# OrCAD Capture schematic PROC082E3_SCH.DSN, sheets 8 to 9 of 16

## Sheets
8 12. FPD LINK_CAM_IN5-8: size C; title: FPD Link Camera  Inputs 5-8
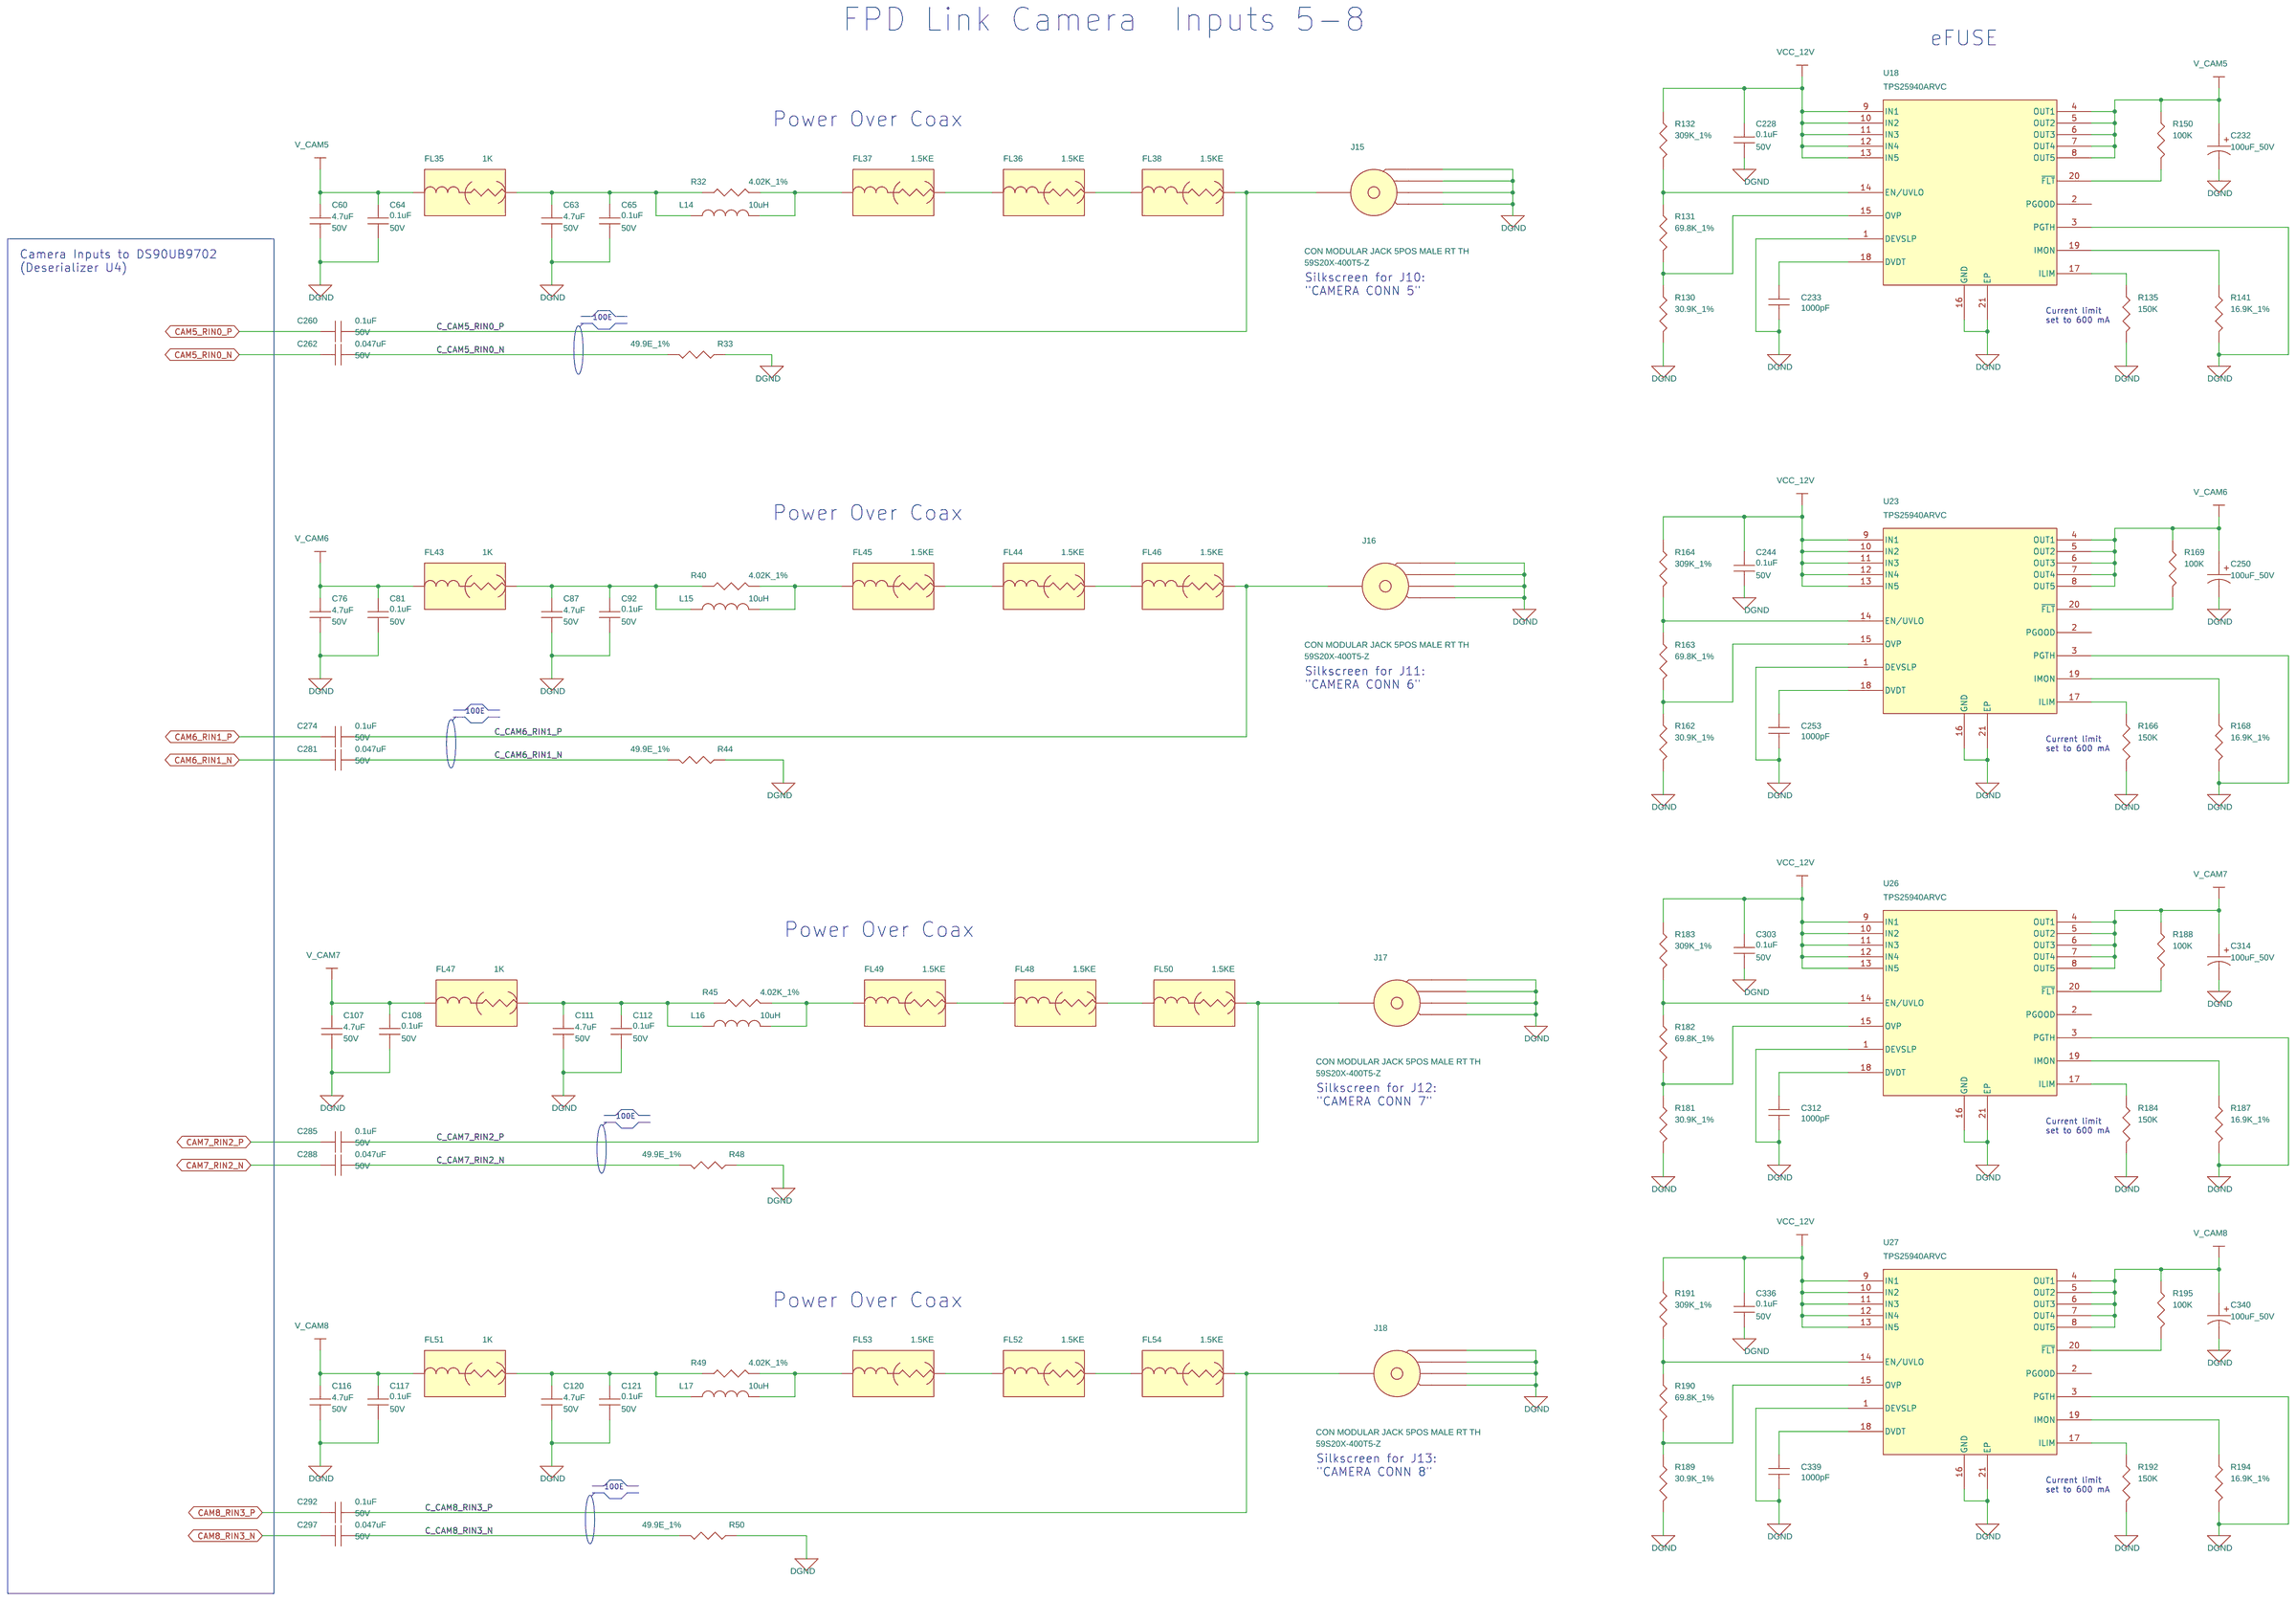
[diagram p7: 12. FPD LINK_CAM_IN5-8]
9 13. FPD LINK_CAM_IN9-12: size C; title: FPD Link Camera  Inputs 5-8
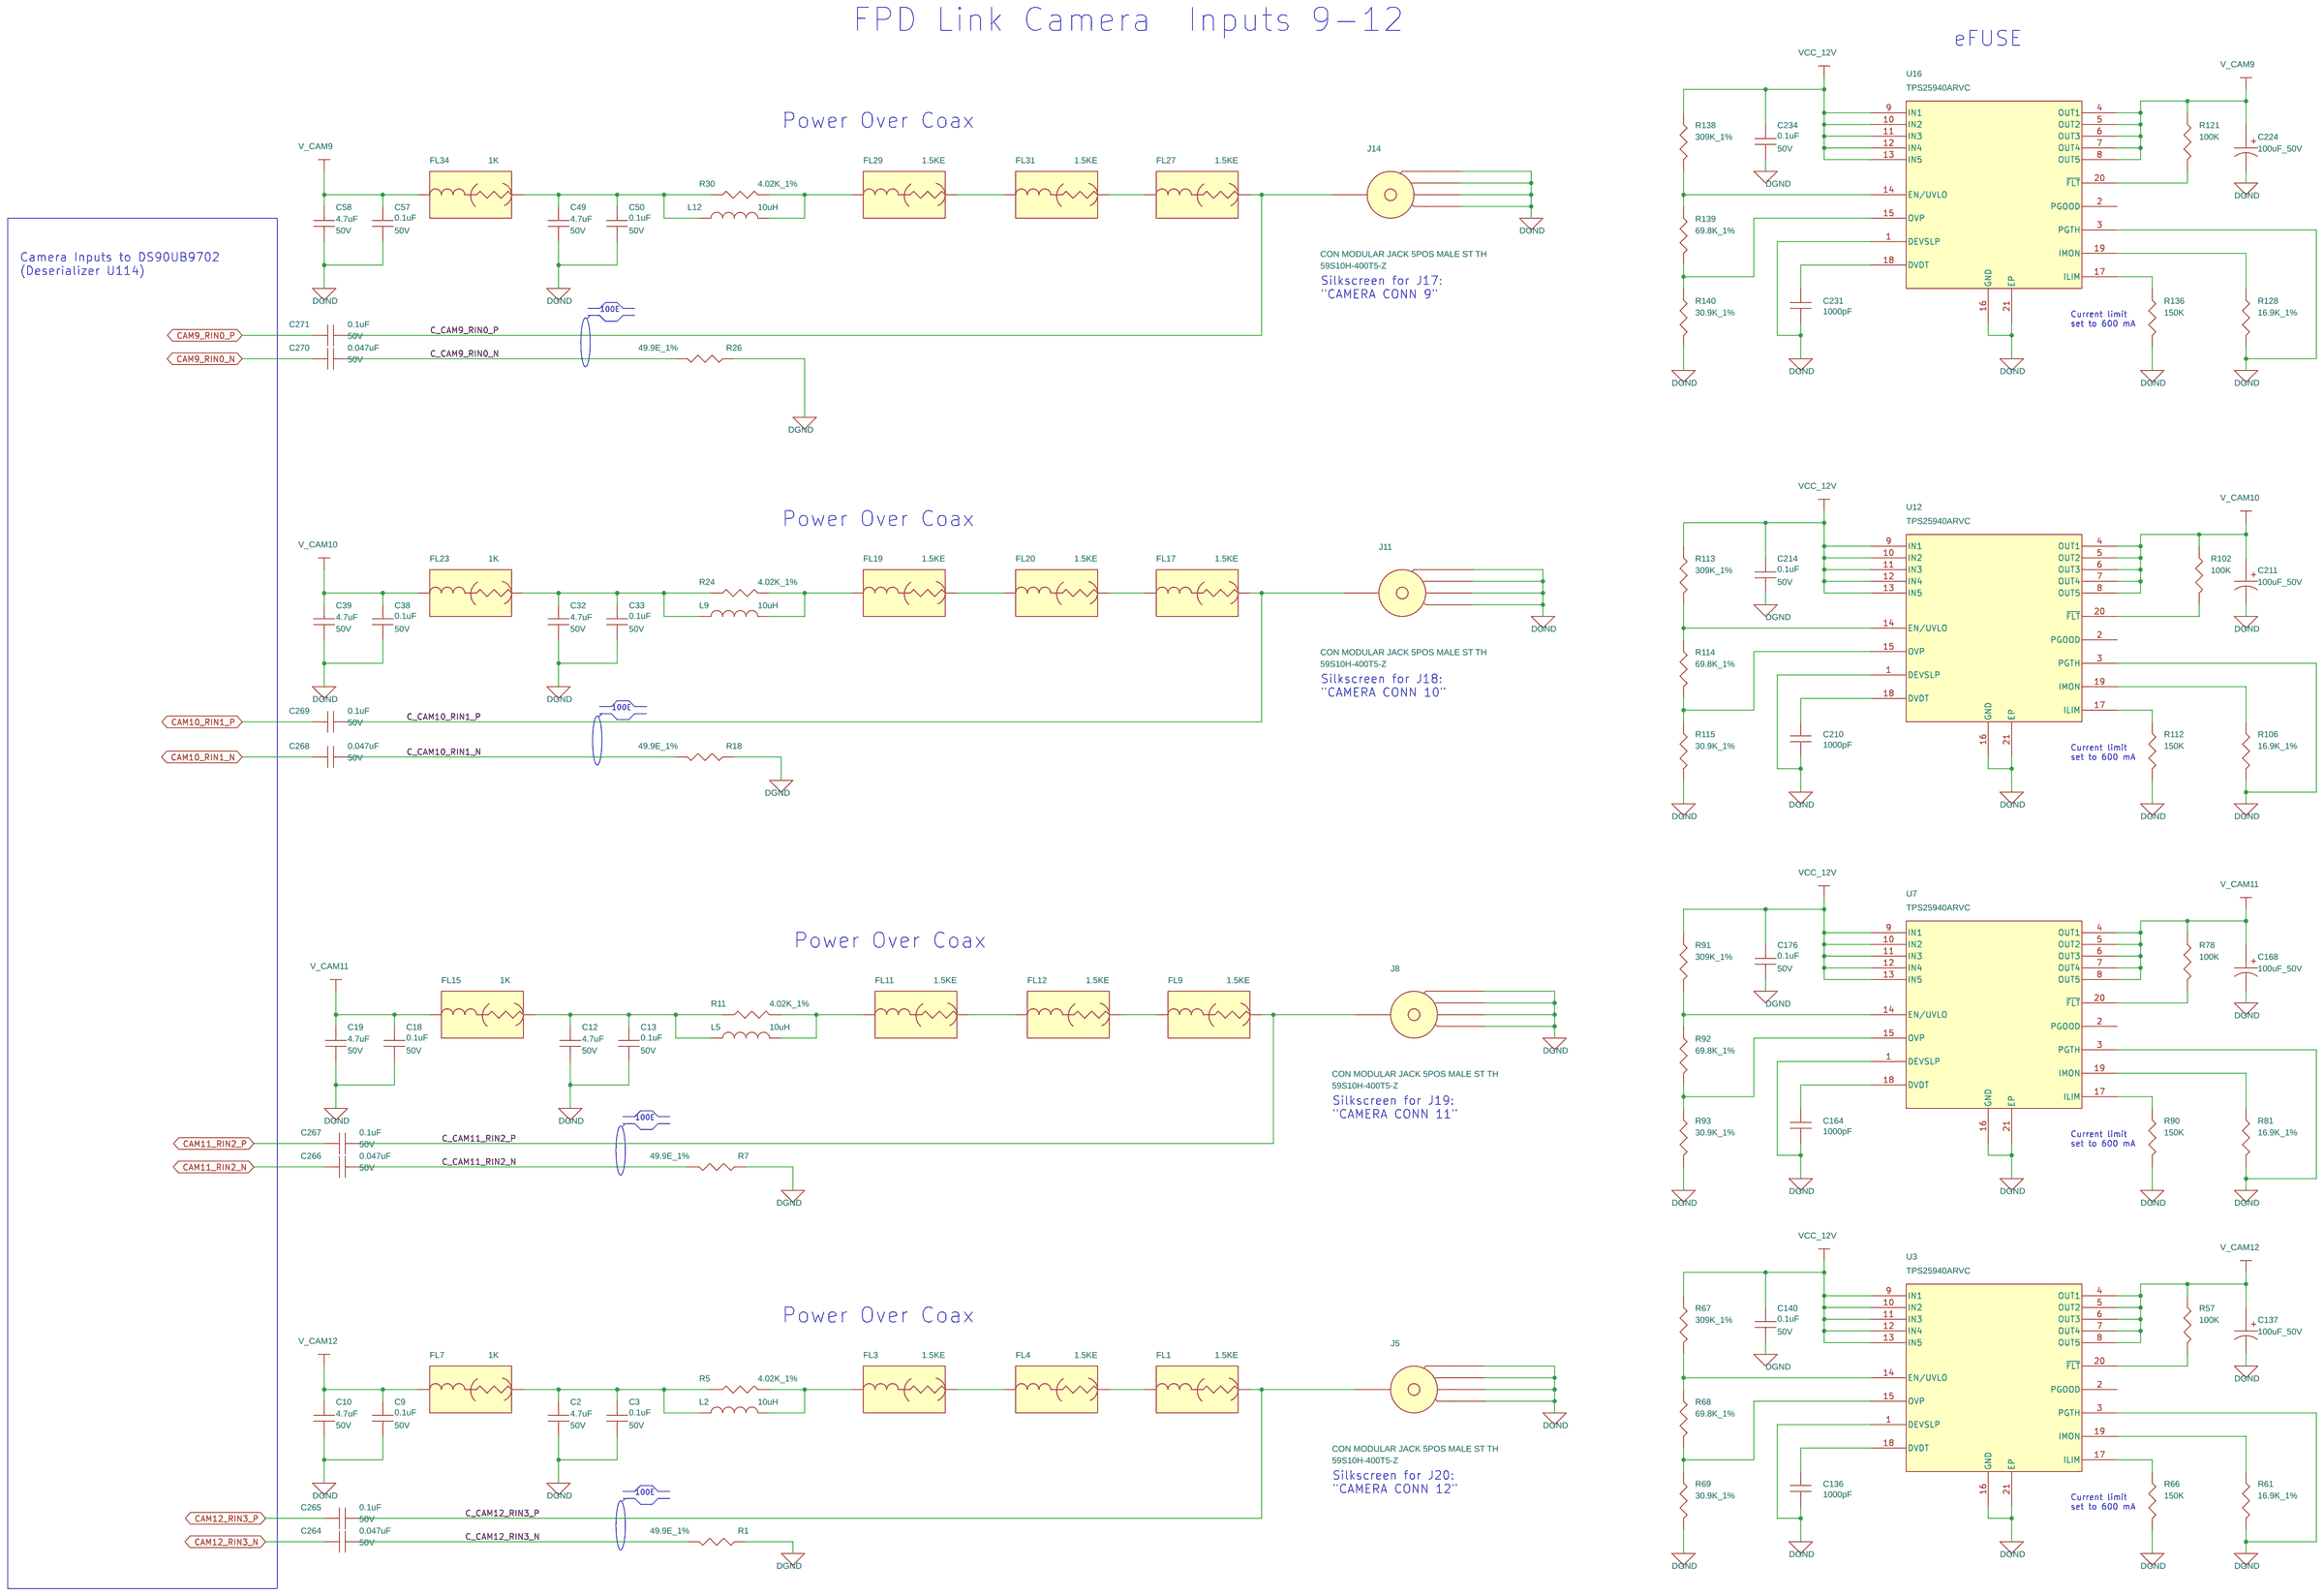
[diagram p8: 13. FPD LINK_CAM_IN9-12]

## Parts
sheet 12. FPD LINK_CAM_IN5-8
C60  4.7uF  [CAP1206_2]
C63  4.7uF  [CAP1206_2]
C64  0.1uF  [CAP0402_0-75]
C65  0.1uF  [CAP0402_0-75]
C76  4.7uF  [CAP1206_2]
C81  0.1uF  [CAP0402_0-75]
C87  4.7uF  [CAP1206_2]
C92  0.1uF  [CAP0402_0-75]
C107  4.7uF  [CAP1206_2]
C108  0.1uF  [CAP0402_0-75]
C111  4.7uF  [CAP1206_2]
C112  0.1uF  [CAP0402_0-75]
C116  4.7uF  [CAP1206_2]
C117  0.1uF  [CAP0402_0-75]
C120  4.7uF  [CAP1206_2]
C121  0.1uF  [CAP0402_0-75]
C228  0.1uF  [CAP0402_0-75]
C232  100uF_50V  [CAPAE_D8CASE_8]
C233  1000pF  [CAP0402_0-75]
C244  0.1uF  [CAP0402_0-75]
C250  100uF_50V  [CAPAE_D8CASE_8]
C253  1000pF  [CAP0402_0-75]
C260  0.1uF  [CAP0402_0-75]
C262  0.047uF  [CAP0402_0-75]
C274  0.1uF  [CAP0402_0-75]
C281  0.047uF  [CAP0402_0-75]
C285  0.1uF  [CAP0402_0-75]
C288  0.047uF  [CAP0402_0-75]
C292  0.1uF  [CAP0402_0-75]
C297  0.047uF  [CAP0402_0-75]
C303  0.1uF  [CAP0402_0-75]
C312  1000pF  [CAP0402_0-75]
C314  100uF_50V  [CAPAE_D8CASE_8]
C336  0.1uF  [CAP0402_0-75]
C339  1000pF  [CAP0402_0-75]
C340  100uF_50V  [CAPAE_D8CASE_8]
FL35  1K  [EMIFIL_BLM18A_0603_1]
FL36  1.5KE  [EMIFIL_BLM18R_0603]
FL37  1.5KE  [EMIFIL_BLM18R_0603]
FL38  1.5KE  [EMIFIL_BLM18R_0603]
FL43  1K  [EMIFIL_BLM18A_0603_1]
FL44  1.5KE  [EMIFIL_BLM18R_0603]
FL45  1.5KE  [EMIFIL_BLM18R_0603]
FL46  1.5KE  [EMIFIL_BLM18R_0603]
FL47  1K  [EMIFIL_BLM18A_0603_1]
FL48  1.5KE  [EMIFIL_BLM18R_0603]
FL49  1.5KE  [EMIFIL_BLM18R_0603]
FL50  1.5KE  [EMIFIL_BLM18R_0603]
FL51  1K  [EMIFIL_BLM18A_0603_1]
FL52  1.5KE  [EMIFIL_BLM18R_0603]
FL53  1.5KE  [EMIFIL_BLM18R_0603]
FL54  1.5KE  [EMIFIL_BLM18R_0603]
J15  CON_JACK5_59S20X-400T5  [CON_JACK5_59S20X-400T5-Z_P_R_T_10-1]
J16  CON_JACK5_59S20X-400T5  [CON_JACK5_59S20X-400T5-Z_P_R_T_10-1]
J17  CON_JACK5_59S20X-400T5  [CON_JACK5_59S20X-400T5-Z_P_R_T_10-1]
J18  CON_JACK5_59S20X-400T5  [CON_JACK5_59S20X-400T5-Z_P_R_T_10-1]
L14  10uH  [IND_MLZ2012N_90X60_SMD]
L15  10uH  [IND_MLZ2012N_90X60_SMD]
L16  10uH  [IND_MLZ2012N_90X60_SMD]
L17  10uH  [IND_MLZ2012N_90X60_SMD]
R32  4.02K_1%  [RES0603_0-5]
R33  49.9E_1%  [RES0402_0-5]
R40  4.02K_1%  [RES0603_0-5]
R44  49.9E_1%  [RES0402_0-5]
R45  4.02K_1%  [RES0603_0-5]
R48  49.9E_1%  [RES0402_0-5]
R49  4.02K_1%  [RES0603_0-5]
R50  49.9E_1%  [RES0402_0-5]
R130  30.9K_1%  [RES0402_0-5]
R131  69.8K_1%  [RES0402_0-5]
R132  309K_1%  [RES0402_0-5]
R135  150K  [RES0402_0-5]
R141  16.9K_1%  [RES0402_0-5]
R150  100K  [RES0402_0-5]
R162  30.9K_1%  [RES0402_0-5]
R163  69.8K_1%  [RES0402_0-5]
R164  309K_1%  [RES0402_0-5]
R166  150K  [RES0402_0-5]
R168  16.9K_1%  [RES0402_0-5]
R169  100K  [RES0402_0-5]
R181  30.9K_1%  [RES0402_0-5]
R182  69.8K_1%  [RES0402_0-5]
R183  309K_1%  [RES0402_0-5]
R184  150K  [RES0402_0-5]
R187  16.9K_1%  [RES0402_0-5]
R188  100K  [RES0402_0-5]
R189  30.9K_1%  [RES0402_0-5]
R190  69.8K_1%  [RES0402_0-5]
R191  309K_1%  [RES0402_0-5]
R192  150K  [RES0402_0-5]
R194  16.9K_1%  [RES0402_0-5]
R195  100K  [RES0402_0-5]
U18  TPS25940ARVC  [QFN20_19-68_120X160_0-8]
U23  TPS25940ARVC  [QFN20_19-68_120X160_0-8]
U26  TPS25940ARVC  [QFN20_19-68_120X160_0-8]
U27  TPS25940ARVC  [QFN20_19-68_120X160_0-8]
sheet 13. FPD LINK_CAM_IN9-12
C2  4.7uF  [CAP1206_2]
C3  0.1uF  [CAP0402_0-75]
C9  0.1uF  [CAP0402_0-75]
C10  4.7uF  [CAP1206_2]
C12  4.7uF  [CAP1206_2]
C13  0.1uF  [CAP0402_0-75]
C18  0.1uF  [CAP0402_0-75]
C19  4.7uF  [CAP1206_2]
C32  4.7uF  [CAP1206_2]
C33  0.1uF  [CAP0402_0-75]
C38  0.1uF  [CAP0402_0-75]
C39  4.7uF  [CAP1206_2]
C49  4.7uF  [CAP1206_2]
C50  0.1uF  [CAP0402_0-75]
C57  0.1uF  [CAP0402_0-75]
C58  4.7uF  [CAP1206_2]
C136  1000pF  [CAP0402_0-75]
C137  100uF_50V  [CAPAE_D8CASE_8]
C140  0.1uF  [CAP0402_0-75]
C164  1000pF  [CAP0402_0-75]
C168  100uF_50V  [CAPAE_D8CASE_8]
C176  0.1uF  [CAP0402_0-75]
C210  1000pF  [CAP0402_0-75]
C211  100uF_50V  [CAPAE_D8CASE_8]
C214  0.1uF  [CAP0402_0-75]
C224  100uF_50V  [CAPAE_D8CASE_8]
C231  1000pF  [CAP0402_0-75]
C234  0.1uF  [CAP0402_0-75]
C264  0.047uF  [CAP0402_0-75]
C265  0.1uF  [CAP0402_0-75]
C266  0.047uF  [CAP0402_0-75]
C267  0.1uF  [CAP0402_0-75]
C268  0.047uF  [CAP0402_0-75]
C269  0.1uF  [CAP0402_0-75]
C270  0.047uF  [CAP0402_0-75]
C271  0.1uF  [CAP0402_0-75]
FL1  1.5KE  [EMIFIL_BLM18R_0603]
FL3  1.5KE  [EMIFIL_BLM18R_0603]
FL4  1.5KE  [EMIFIL_BLM18R_0603]
FL7  1K  [EMIFIL_BLM18A_0603_1]
FL9  1.5KE  [EMIFIL_BLM18R_0603]
FL11  1.5KE  [EMIFIL_BLM18R_0603]
FL12  1.5KE  [EMIFIL_BLM18R_0603]
FL15  1K  [EMIFIL_BLM18A_0603_1]
FL17  1.5KE  [EMIFIL_BLM18R_0603]
FL19  1.5KE  [EMIFIL_BLM18R_0603]
FL20  1.5KE  [EMIFIL_BLM18R_0603]
FL23  1K  [EMIFIL_BLM18A_0603_1]
FL27  1.5KE  [EMIFIL_BLM18R_0603]
FL29  1.5KE  [EMIFIL_BLM18R_0603]
FL31  1.5KE  [EMIFIL_BLM18R_0603]
FL34  1K  [EMIFIL_BLM18A_0603_1]
J5  CON_JACK5_59S10H-400T5  [CON_JACK5_59S10H-400T5-Z_P_S_T_12-5]
J8  CON_JACK5_59S10H-400T5  [CON_JACK5_59S10H-400T5-Z_P_S_T_12-5]
J11  CON_JACK5_59S10H-400T5  [CON_JACK5_59S10H-400T5-Z_P_S_T_12-5]
J14  CON_JACK5_59S10H-400T5  [CON_JACK5_59S10H-400T5-Z_P_S_T_12-5]
L2  10uH  [IND_MLZ2012N_90X60_SMD]
L5  10uH  [IND_MLZ2012N_90X60_SMD]
L9  10uH  [IND_MLZ2012N_90X60_SMD]
L12  10uH  [IND_MLZ2012N_90X60_SMD]
R1  49.9E_1%  [RES0402_0-5]
R5  4.02K_1%  [RES0603_0-5]
R7  49.9E_1%  [RES0402_0-5]
R11  4.02K_1%  [RES0603_0-5]
R18  49.9E_1%  [RES0402_0-5]
R24  4.02K_1%  [RES0603_0-5]
R26  49.9E_1%  [RES0402_0-5]
R30  4.02K_1%  [RES0603_0-5]
R57  100K  [RES0402_0-5]
R61  16.9K_1%  [RES0402_0-5]
R66  150K  [RES0402_0-5]
R67  309K_1%  [RES0402_0-5]
R68  69.8K_1%  [RES0402_0-5]
R69  30.9K_1%  [RES0402_0-5]
R78  100K  [RES0402_0-5]
R81  16.9K_1%  [RES0402_0-5]
R90  150K  [RES0402_0-5]
R91  309K_1%  [RES0402_0-5]
R92  69.8K_1%  [RES0402_0-5]
R93  30.9K_1%  [RES0402_0-5]
R102  100K  [RES0402_0-5]
R106  16.9K_1%  [RES0402_0-5]
R112  150K  [RES0402_0-5]
R113  309K_1%  [RES0402_0-5]
R114  69.8K_1%  [RES0402_0-5]
R115  30.9K_1%  [RES0402_0-5]
R121  100K  [RES0402_0-5]
R128  16.9K_1%  [RES0402_0-5]
R136  150K  [RES0402_0-5]
R138  309K_1%  [RES0402_0-5]
R139  69.8K_1%  [RES0402_0-5]
R140  30.9K_1%  [RES0402_0-5]
U3  TPS25940ARVC  [QFN20_19-68_120X160_0-8]
U7  TPS25940ARVC  [QFN20_19-68_120X160_0-8]
U12  TPS25940ARVC  [QFN20_19-68_120X160_0-8]
U16  TPS25940ARVC  [QFN20_19-68_120X160_0-8]

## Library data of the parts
C2 C10 C12 C19 C32 C39 C49 C58 C60 C63 C76 C87 C107 C111 C116 C120 = CAP: CAP CERAMIC 4.7uF 50V 10% X7R 1206; Chkd/date: VASANTHA/100315; Crtd /date: NAVEED/240714; Custom_Duty: 15%; Customs_HS_Code: 85322990; Distributor_name: DIGIKEY; Distributor_part_number: 587-2994-1-ND; Footprint Path: Y:\MIS_DATABASE\Library\ALTIUM_TOOL\PCB_FOOTPRINTS\Altium_Footprint_Lib.PcbLib; Height: 1.80MM; Library Path: Y:\MIS_DATABASE\Library\ALTIUM_TOOL\SCHEMATICS_PARTS\MS_DISCRETE_Library.schlib; Mfr_name: TAIYO YUDEN; Mfr_part_number: UMK316AB7475KL-T; Mistral Part No: 120014070019-R; Package: 1206; Part_type: CAPACITORS\CERAMIC; Project: MS_ADE_PSM_PSU; RoHS: RoHS; Temperature: -55°C+125°C; Tolerance: 10%; Voltage: 50V; Wattage: NA; Weight: 16.2mg; Datasheet: Y:\MIS_DATABASE\DATASHEETS\CAPACITORS\UMK316AB7475KL-T.PDF
C3 C9 C13 C18 C33 C38 C50 C57 C64 C65 C81 C92 C108 C112 C117 C121 C140 C176 C214 C228 C234 C244 C260 C265 C267 C269 C271 C274 C285 C292 C303 C336 = CAP: CAP CERAMIC 0.1uF 50V 10% X7R 0402; Chkd/date: MANIRAJA/131217; Crtd /date: ALVY/131217; Custom_Duty: 15%; Customs_HS_Code: 85322990; Distributor_name: DIGIKEY; Distributor_part_number: 478-10043-1-ND; Footprint Path: Y:\MIS_DATABASE\Library\ALTIUM_TOOL\PCB_FOOTPRINTS\Altium_Footprint_Lib.PcbLib; Height: 0.56MM; Library Path: Y:\MIS_DATABASE\Library\ALTIUM_TOOL\SCHEMATICS_PARTS\MS_DISCRETE_Library.schlib; Mfr_name: AVX CORPORATION; Mfr_part_number: 04025C104KAT2A; Mistral Part No: 120011100014-R; Package: 0402; Part_type: CAPACITORS\CERAMIC; Project: ASL_LIU_TYPE-II; RoHS: RoHS; Temperature: -55°C+125°C; Tolerance: 10%; Voltage: 50V; Wattage: NA; Weight: 0.65mg; Datasheet: Y:\MIS_DATABASE\DATASHEETS\CAPACITORS\AVX_MLC.PDF
C137 C168 C211 C224 C232 C250 C314 C340 = CAP_POL: CAP ELECTROLYTIC 100uF 50V 20% D8CASE_6666; Chkd/date: MANIRAJA/051018; Crtd /date: ALVY/051018; Custom_Duty: 15%; Customs_HS_Code: 85322990; Distributor_name: DIGIKEY; Distributor_part_number: PCE5024CT-ND; Footprint Path: Y:\MIS_DATABASE\Library\ALTIUM_TOOL\PCB_FOOTPRINTS\Altium_Footprint_Lib.PcbLib; Height: 8.00MM; Library Path: Y:\MIS_DATABASE\Library\ALTIUM_TOOL\SCHEMATICS_PARTS\MS_DISCRETE_Library.schlib; Mfr_name: PANASONIC-ECG; Mfr_part_number: EEE-FTH101XAP; Mistral Part No: 120018100013-R; Package: D8CASE_6666; Part_type: CAPACITORS\ELECTROLYTIC; Project: TI_J7_SVB-DUT; RoHS: RoHS; Temperature: -55°C+105°C; Tolerance: 20%; Voltage: 50V; Wattage: NA; Weight: 440mg; Datasheet: Y:\MIS_DATABASE\DATASHEETS\CAPACITORS\FTV-SER.PDF
C136 C164 C210 C231 C233 C253 C312 C339 = CAP: CAP CERAMIC 1000pF 50V 5% C0G(NP0) 0402; Chkd/date: VASANTHA/281216; Crtd /date: MAZHAR/290806; Custom_Duty: 15%; Customs_HS_Code: 85322990; Distributor_name: DIGIKEY; Distributor_part_number: 490-3244-1-ND; Footprint Path: Y:\MIS_DATABASE\Library\ALTIUM_TOOL\PCB_FOOTPRINTS\Altium_Footprint_Lib.PcbLib; Height: 0.55MM; Library Path: Y:\MIS_DATABASE\Library\ALTIUM_TOOL\SCHEMATICS_PARTS\MS_DISCRETE_Library.schlib; Mfr_name: MURATA; Mfr_part_number: GRM1555C1H102JA01D; Mistral Part No: 120016110009-R; Package: 0402; Part_type: CAPACITORS\CERAMIC; Project: SVDO_RMB_MMA; RoHS: RoHS; Temperature: -55°C+125°C; Tolerance: 5%; Voltage: 50V; Wattage: NA; Weight: 6mg; Datasheet: Y:\MIS_DATABASE\DATASHEETS\CAPACITORS\MURATA-GXX-SER_NOV17.PDF
C262 C264 C266 C268 C270 C281 C288 C297 = CAP: CAP CERAMIC 0.047uF 50V 10% X7R 0402; Chkd/date: MANIRAJA/240118; Crtd /date: MANIRAJA/240118; Custom_Duty: 15%; Customs_HS_Code: 85322990; Distributor_name: DIGIKEY; Distributor_part_number: GRM155R71H473KE14J-ND; Footprint Path: Y:\MIS_DATABASE\Library\ALTIUM_TOOL\PCB_FOOTPRINTS\Altium_Footprint_Lib.PcbLib; Height: 0.55MM; Library Path: Y:\MIS_DATABASE\Library\ALTIUM_TOOL\SCHEMATICS_PARTS\MS_DISCRETE_Library.schlib; Mfr_name: MURATA; Mfr_part_number: GRM155R71H473KE14J; Mistral Part No: 120018010011-R; Package: 0402; Part_type: CAPACITORS\CERAMIC; Project: TI_MAXIE_CPB; RoHS: RoHS; Temperature: -55°C+125°C; Tolerance: 10%; Voltage: 50V; Wattage: NA; Weight: 6mg; Datasheet: Y:\MIS_DATABASE\DATASHEETS\CAPACITORS\GRM155R71H473KE14.PDF
FL7 FL15 FL23 FL34 FL35 FL43 FL47 FL51 = EMIFILTER_IND: IND FERRITE BEAD CHIP 1K 450mA 0603; Chkd/date: MANIRAJA/070818; Crtd /date: USMAN/070409; Custom_Duty: 24%; Customs_HS_Code: 85437099; Distributor_name: DIGIKEY; Distributor_part_number: 490-1015-1-ND; Footprint Path: Y:\MIS_DATABASE\Library\ALTIUM_TOOL\PCB_FOOTPRINTS\Altium_Footprint_Lib.PcbLib; Height: 0.95MM; Library Path: Y:\MIS_DATABASE\Library\ALTIUM_TOOL\SCHEMATICS_PARTS\MS_DISCRETE_Library.schlib; Mfr_name: MURATA; Mfr_part_number: BLM18AG102SN1D; Mistral Part No: 130009070006-R; Package: 0603; Part_type: INDUCTOR; Project: AARDK; RoHS: RoHS; Temperature: -55°C+125°C; Tolerance: 25%; Voltage: NA; Wattage: NA; Weight: 5mg; Datasheet: Y:\MIS_DATABASE\DATASHEETS\DISCRETES\INDUCTORS\BLM18A-N1.PDF
FL1 FL3 FL4 FL9 FL11 FL12 FL17 FL19 FL20 FL27 FL29 FL31 FL36-FL38 FL44-FL46 FL48-FL50 FL52-FL54 = EMIFILTER_IND: FERRITE BEAD 1.5KE 500MA 0603; Chkd/date: RAGESH/111010; Crtd /date: MUDDU/050210; Custom_Duty: 24%; Customs_HS_Code: 85437099; Distributor_name: DIGIKEY; Distributor_part_number: 490-5216-1-ND; Footprint Path: Y:\MIS_DATABASE\Library\ALTIUM_TOOL\PCB_FOOTPRINTS\Altium_Footprint_Lib.PcbLib; Height: 0.95MM; Library Path: Y:\MIS_DATABASE\Library\ALTIUM_TOOL\SCHEMATICS_PARTS\MS_FILTER_Library.schlib; Mfr_name: MURATA; Mfr_part_number: BLM18HE152SN1; Mistral Part No: 130010020011; Package: 0603; Part_type: FILTER; Project: NPOL_CONTROLLERCARD; Temperature: -55°C+125°C; Tolerance: NA; Voltage: NA; Wattage: NA; Weight: NA; Datasheet: Y:\MIS_DATABASE\DATASHEETS\DISCRETES\INDUCTORS\BLM18H.PDF
J15-J18 = CON5_MCXJACK_TH: CON MODULAR JACK 5POS MALE RT TH; Chkd/date: MANIRAJA/020519; Crtd /date: MANIRAJA/020519; Custom_Duty: 24%; Customs_HS_Code: 85369090; Distributor_name: NA; Distributor_part_number: NA; Footprint Path: Y:\MIS_DATABASE\Library\ALTIUM_TOOL\PCB_FOOTPRINTS\Altium_Footprint_Lib.PcbLib; Height: 10.05MM; Library Path: Y:\MIS_DATABASE\Library\ALTIUM_TOOL\SCHEMATICS_PARTS\MS_CONNECTOR_Library.schlib; Mfr_name: ROSENBERGER; Mfr_part_number: 59S20X-400T5-Z; Mistral Part No: 150019050002-R; Package: THRU-HOLE; Part_type: CONNECTOR\JACK; Project: TI_J7ES_EVM_FUSION2_SER_CAP; RoHS: RoHS; Temperature: -40°C+105°C; Tolerance: NA; Voltage: NA; Wattage: NA; Weight: 3880mg; Datasheet: Y:\MIS_DATABASE\DATASHEETS\CONNECTORS\59S20X-400T5-Y.PDF
L2 L5 L9 L12 L14-L17 = INDUCTOR: IND 10uH 20% 500mA SMD; Alternate_mfr_name_A: TDK CORPORATION; Alternate_mfr_part_number_A: MLZ2012N100LT000; Chkd/date: BALACHANDAR/150514; Crtd /date: SARANYA/120514; Custom_Duty: 24%; Customs_HS_Code: 85437099; Distributor_name: MOUSER; Distributor_name_A: DIGIKEY; Distributor_part_number: 810-MLZ2012N100L; Distributor_part_number_A: 445-6762-1-ND; Height: 1.25MM; Mfr_name: TDK CORPORATION; Mfr_part_number: MLZ2012N100L; Mistral Part No: 130014050064-R; Package: 0805; Project: AEGIS GP BETA2; RoHS: RoHS; Temperature: -55°C+125°C; Tolerance: NA; Voltage: NA; Wattage: NA; Weight: 14mg; Datasheet: Y:\MIS_DATABASE\DATASHEETS\DISCRETES\INDUCTORS\MLZ2012_SERIES.PDF
R5 R11 R24 R30 R32 R40 R45 R49 = RESISTOR: RES 4.02K 1/10W 1% 0603; Chkd/date: VASANTHA/201216; Crtd /date: MAZHAR/241109; Custom_Duty: 15%; Customs_HS_Code: 85332119; Distributor_name: DIGIKEY; Distributor_part_number: 541-4.02KHCT-ND; Footprint Path: Y:\MIS_DATABASE\Library\ALTIUM_TOOL\PCB_FOOTPRINTS\Altium_Footprint_Lib.PcbLib; Height: 0.50MM; Library Path: Y:\MIS_DATABASE\Library\ALTIUM_TOOL\SCHEMATICS_PARTS\MS_DISCRETE_Library.schlib; Mfr_name: VISHAY; Mfr_part_number: CRCW06034K02FKEA; Mistral Part No: 110009110009-R; Package: 0603; Part_type: RESISTORS\FIXED; Project: NPOL_FPS; RoHS: RoHS; Temperature: -55°C+155°C; Tolerance: 1%; Voltage: NA; Wattage: 1/10W; Weight: 2mg; Datasheet: Y:\MIS_DATABASE\DATASHEETS\RESISTORS\CRCW0603.PDF
R1 R7 R18 R26 R33 R44 R48 R50 = RESISTOR: RES 49.9E 1/10W 1% 0402; Chkd/date: VASANTHA/201216; Crtd /date: MAZHAR/201005; Custom_Duty: 15%; Customs_HS_Code: 85332119; Distributor_name: DIGIKEY; Distributor_part_number: P49.9LCT-ND; Footprint Path: Y:\MIS_DATABASE\Library\ALTIUM_TOOL\PCB_FOOTPRINTS\Altium_Footprint_Lib.PcbLib; Height: 0.40MM; Library Path: Y:\MIS_DATABASE\Library\ALTIUM_TOOL\SCHEMATICS_PARTS\MS_DISCRETE_Library.schlib; Mfr_name: PANASONIC-ECG; Mfr_part_number: ERJ-2RKF49R9X; Mistral Part No: 110009030897-R; Package: 0402; Part_type: RESISTORS\FIXED; Project: RED EYE; RoHS: RoHS; Temperature: -55°C+155°C; Tolerance: 1%; Voltage: NA; Wattage: 1/10W; Weight: 0.8mg; Datasheet: Y:\MIS_DATABASE\DATASHEETS\RESISTORS\PAN-ERJSER_NOV17.PDF
R69 R93 R115 R130 R140 R162 R181 R189 = RESISTOR: RES 30.9K 1/10W 1% 0402; Chkd/date: MAZHAR/080311; Crtd /date: BAVISH/230211; Custom_Duty: 15%; Customs_HS_Code: 85332119; Distributor_name: DIGIKEY; Distributor_part_number: P30.9KLCT-ND; Footprint Path: Y:\MIS_DATABASE\Library\ALTIUM_TOOL\PCB_FOOTPRINTS\Altium_Footprint_Lib.PcbLib; Height: 0.40MM; Library Path: Y:\MIS_DATABASE\Library\ALTIUM_TOOL\SCHEMATICS_PARTS\MS_DISCRETE_Library.schlib; Mfr_name: PANASONIC-ECG; Mfr_part_number: ERJ-2RKF3092X; Mistral Part No: 110011020022-R; Package: 0402; Part_type: RESISTORS\FIXED; Project: GOLDEN-I; RoHS: RoHS; Temperature: -55°C+155°C; Tolerance: 1%; Voltage: NA; Wattage: 1/10W; Weight: 0.8mg; Datasheet: Y:\MIS_DATABASE\DATASHEETS\RESISTORS\PAN-ERJSER_NOV17.PDF
R68 R92 R114 R131 R139 R163 R182 R190 = RESISTOR: RES 69.8K 1/10W 1% 0402; Chkd/date: SHREESHAIL/121205; Crtd /date: MAZHAR/030605; Custom_Duty: 15%; Customs_HS_Code: 85332119; Distributor_name: DIGIKEY; Distributor_part_number: P69.8KLCT-ND; Footprint Path: Y:\MIS_DATABASE\Library\ALTIUM_TOOL\PCB_FOOTPRINTS\Altium_Footprint_Lib.PcbLib; Height: 0.40MM; Library Path: Y:\MIS_DATABASE\Library\ALTIUM_TOOL\SCHEMATICS_PARTS\MS_DISCRETE_Library.schlib; Mfr_name: PANASONIC-ECG; Mfr_part_number: ERJ-2RKF6982X; Mistral Part No: 110009031082-R; Package: 0402; Part_type: RESISTORS\FIXED; Project: G4SLIM; RoHS: RoHS; Temperature: -55°C+155°C; Tolerance: 1%; Voltage: NA; Wattage: 1/10W; Weight: 0.8mg; Datasheet: Y:\MIS_DATABASE\DATASHEETS\RESISTORS\PAN-ERJSER_NOV17.PDF
R67 R91 R113 R132 R138 R164 R183 R191 = RESISTOR: RES 309K 1/10W 1% 0402; Chkd/date: JEBRAN/060215; Crtd /date: USMAN/140313; Custom_Duty: 15%; Customs_HS_Code: 85332119; Distributor_name: DIGIKEY; Distributor_part_number: P309KLCT-ND; Footprint Path: Y:\MIS_DATABASE\Library\ALTIUM_TOOL\PCB_FOOTPRINTS\Altium_Footprint_Lib.PcbLib; Height: 0.40MM; Library Path: Y:\MIS_DATABASE\Library\ALTIUM_TOOL\SCHEMATICS_PARTS\MS_DISCRETE_Library.schlib; Mfr_name: PANASONIC-ECG; Mfr_part_number: ERJ-2RKF3093X; Mistral Part No: 110013030008-R; Package: 0402; Part_type: RESISTORS\FIXED; Project: DTRM; RoHS: RoHS; Temperature: -55°C+155°C; Tolerance: 1%; Voltage: NA; Wattage: 1/10W; Weight: 0.8mg; Datasheet: Y:\MIS_DATABASE\DATASHEETS\RESISTORS\PAN-ERJSER_NOV17.PDF
R66 R90 R112 R135 R136 R166 R184 R192 = RESISTOR: RES 150K 1/10W 5% 0402; Chkd/date: MANIRAJA/150419; Crtd /date: ALVY/150419; Custom_Duty: 15%; Customs_HS_Code: 85332119; Distributor_name: DIGIKEY; Distributor_part_number: P150KJCT-ND; Footprint Path: Y:\MIS_DATABASE\Library\ALTIUM_TOOL\PCB_FOOTPRINTS\Altium_Footprint_Lib.PcbLib; Height: 0.40MM; Library Path: Y:\MIS_DATABASE\Library\ALTIUM_TOOL\SCHEMATICS_PARTS\MS_DISCRETE_Library.schlib; Mfr_name: PANASONIC-ECG; Mfr_part_number: ERJ-2GEJ154X; Mistral Part No: 110019040287-R; Package: 0402; Part_type: RESISTORS\FIXED; Project: TI_J7ES_EVM_FUSION2_SER_CAP; RoHS: RoHS; Temperature: -55°C+155°C; Tolerance: 5%; Voltage: NA; Wattage: 1/10W; Weight: 0.8mg; Datasheet: Y:\MIS_DATABASE\DATASHEETS\RESISTORS\PAN-ERJSER_NOV17.PDF
R61 R81 R106 R128 R141 R168 R187 R194 = RESISTOR: RES 16.9K 1/10W 1% 0402; Chkd/date: SHREESHAIL/24050; Crtd /date: MAZHAR/260706; Custom_Duty: 15%; Customs_HS_Code: 85332119; Distributor_name: DIGIKEY; Distributor_part_number: P16.9KLCT-ND; Footprint Path: Y:\MIS_DATABASE\Library\ALTIUM_TOOL\PCB_FOOTPRINTS\Altium_Footprint_Lib.PcbLib; Height: 0.40MM; Library Path: Y:\MIS_DATABASE\Library\ALTIUM_TOOL\SCHEMATICS_PARTS\MS_DISCRETE_Library.schlib; Mfr_name: PANASONIC-ECG; Mfr_part_number: ERJ-2RKF1692X; Mistral Part No: 110009030351-R; Package: 0402; Part_type: RESISTORS\FIXED; Project: POWERBOX; RoHS: RoHS; Temperature: -55°C+155°C; Tolerance: 1%; Voltage: NA; Wattage: 1/10W; Weight: 0.8mg; Datasheet: Y:\MIS_DATABASE\DATASHEETS\RESISTORS\PAN-ERJSER_NOV17.PDF
R57 R78 R102 R121 R150 R169 R188 R195 = RESISTOR: RES 100K 1/16W 5% 0402; Chkd/date: VASANTHA/061216; Crtd /date: BAVISH/010611; Custom_Duty: 15%; Customs_HS_Code: 85332119; Distributor_name: DIGIKEY; Distributor_part_number: 541-100KJCT-ND; Footprint Path: Y:\MIS_DATABASE\Library\ALTIUM_TOOL\PCB_FOOTPRINTS\Altium_Footprint_Lib.PcbLib; Height: 0.40MM; Library Path: Y:\MIS_DATABASE\Library\ALTIUM_TOOL\SCHEMATICS_PARTS\MS_DISCRETE_Library.schlib; Mfr_name: VISHAY; Mfr_part_number: CRCW0402100KJNED; Mistral Part No: 110011060002-R; Package: 0402; Part_type: RESISTORS\FIXED; Project: AM4515_EVM_LCD; RoHS: RoHS; Temperature: -55°C+155°C; Tolerance: 5%; Voltage: NA; Wattage: 1/16W; Weight: 0.65mg; Datasheet: Y:\MIS_DATABASE\DATASHEETS\RESISTORS\CRCW0603.PDF
U3 U7 U12 U16 U18 U23 U26 U27 = TPS25940_WQFN20_TI: IC eFUSE WITH TRUE REVERSE BLOCKING AND DEVSLEEP SUPPORT FOR SSD WQFN20; Chkd/date: MANIRAJA/220818; Crtd /date: ALVY/220818; Custom_Duty: 15%; Customs_HS_Code: 85423100; Distributor_name: DIGIKEY; Distributor_part_number: 296-46233-1-ND; Footprint Path: Y:\MIS_DATABASE\Library\ALTIUM_TOOL\PCB_FOOTPRINTS\Altium_Footprint_Lib.PcbLib; Height: 0.80MM; Library Path: Y:\MIS_DATABASE\Library\ALTIUM_TOOL\SCHEMATICS_PARTS\MS_MISCPOWER_Library.schlib; Library Ref: TPS25940_WQFN20; Mfr_name: TEXAS INSTRUMENTS; Mfr_part_number: TPS25940ARVCR; Mistral Part No: 142018080015-R; Package: WQFN20; Part_type: ICS\POWER\POWER MANAGEMENT; Project: TI_J7ES_EVM_FUSION2_SER_CAP; RoHS: RoHS; Temperature: -40°C+85°C; Tolerance: NA; Voltage: NA; Wattage: NA; Weight: 38.1mg; Datasheet: Y:\MIS_DATABASE\DATASHEETS\ICS\POWER\TPS25940XX.PDF
J5 J8 J11 J14 = CON5_MCXJACK_TH: CON MODULAR JACK 5POS MALE ST TH; Chkd/date: MANIRAJA/020519; Crtd /date: MANIRAJA/020519; Custom_Duty: 24%; Customs_HS_Code: 85369090; Distributor_name: MOUSER; Distributor_part_number: 476-59S10H-400T5-Z; Footprint Path: Y:\MIS_DATABASE\Library\ALTIUM_TOOL\PCB_FOOTPRINTS\Altium_Footprint_Lib.PcbLib; Height: 12.45MM; Library Path: Y:\MIS_DATABASE\Library\ALTIUM_TOOL\SCHEMATICS_PARTS\MS_CONNECTOR_Library.schlib; Mfr_name: ROSENBERGER; Mfr_part_number: 59S10H-400T5-Z; Mistral Part No: 150019050001-R; Package: THRU-HOLE; Part_type: CONNECTOR\JACK; Project: TI_J7ES_EVM_FUSION2_SER_CAP; RoHS: RoHS; Temperature: -40°C+105°C; Tolerance: NA; Voltage: NA; Wattage: NA; Weight: 1650mg; Datasheet: Y:\MIS_DATABASE\DATASHEETS\CONNECTORS\59S10H-400T5-Y.PDF

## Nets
DGND: C2.2 C3.2 C9.2 C10.2 C12.2 C13.2 C18.2 C19.2 C32.2 C33.2 C38.2 C39.2 C49.2 C50.2 C57.2 C58.2 C60.2 C63.2 C64.2 C65.2 C76.2 C81.2 C87.2 C92.2 C107.2 C108.2 C111.2 C112.2 C116.2 C117.2 C120.2 C121.2 C136.2 C137.2 C140.2 C164.2 C168.2 C176.2 C210.2 C211.2 C214.2 C224.2 C228.2 C231.2 C232.2 C233.2 C234.2 C244.2 C250.2 C253.2 C303.2 C312.2 C314.2 C336.2 C339.2 C340.2 J5.2 J5.3 J5.4 J5.5 J8.2 J8.3 J8.4 J8.5 J11.2 J11.3 J11.4 J11.5 J14.2 J14.3 J14.4 J14.5 J15.2 J15.3 J15.4 J15.5 J16.2 J16.3 J16.4 J16.5 J17.2 J17.3 J17.4 J17.5 J18.2 J18.3 J18.4 J18.5 R1.1 R7.1 R18.1 R26.1 R33.1 R44.1 R48.1 R50.1 R61.2 R66.2 R69.2 R81.2 R90.2 R93.2 R106.2 R112.2 R115.2 R128.2 R130.2 R135.2 R136.2 R140.2 R141.2 R162.2 R166.2 R168.2 R181.2 R184.2 R187.2 R189.2 R192.2 R194.2 U3.1(DEVSLP) U3.3(PGTH) U3.16(GND) U3.21(EP) U7.1(DEVSLP) U7.3(PGTH) U7.16(GND) U7.21(EP) U12.1(DEVSLP) U12.3(PGTH) U12.16(GND) U12.21(EP) U16.1(DEVSLP) U16.3(PGTH) U16.16(GND) U16.21(EP) U18.1(DEVSLP) U18.3(PGTH) U18.16(GND) U18.21(EP) U23.1(DEVSLP) U23.3(PGTH) U23.16(GND) U23.21(EP) U26.1(DEVSLP) U26.3(PGTH) U26.16(GND) U26.21(EP) U27.1(DEVSLP) U27.3(PGTH) U27.16(GND) U27.21(EP) ; also on sheet 4 5 6 7 10 11 13 14 15 16
VCC_12V: C140.1 C176.1 C214.1 C228.1 C234.1 C244.1 C303.1 C336.1 R67.1 R91.1 R113.1 R132.1 R138.1 R164.1 R183.1 R191.1 U3.9(IN1) U3.10(IN2) U3.11(IN3) U3.12(IN4) U3.13(IN5) U7.9(IN1) U7.10(IN2) U7.11(IN3) U7.12(IN4) U7.13(IN5) U12.9(IN1) U12.10(IN2) U12.11(IN3) U12.12(IN4) U12.13(IN5) U16.9(IN1) U16.10(IN2) U16.11(IN3) U16.12(IN4) U16.13(IN5) U18.9(IN1) U18.10(IN2) U18.11(IN3) U18.12(IN4) U18.13(IN5) U23.9(IN1) U23.10(IN2) U23.11(IN3) U23.12(IN4) U23.13(IN5) U26.9(IN1) U26.10(IN2) U26.11(IN3) U26.12(IN4) U26.13(IN5) U27.9(IN1) U27.10(IN2) U27.11(IN3) U27.12(IN4) U27.13(IN5) ; also on sheet 11 13 14 15 16
C_CAM5_RIN0_N: C262.1 R33.2
C_CAM5_RIN0_P: C260.1 FL38.2 J15.1
C_CAM6_RIN1_N: C281.1 R44.2
C_CAM6_RIN1_P: C274.1 FL46.2 J16.1
C_CAM7_RIN2_N: C288.1 R48.2
C_CAM7_RIN2_P: C285.1 FL50.2 J17.1
C_CAM8_RIN3_N: C297.1 R50.2
C_CAM8_RIN3_P: C292.1 FL54.2 J18.1
C_CAM9_RIN0_N: C270.1 R26.2
C_CAM9_RIN0_P: C271.1 FL27.2 J14.1
C_CAM10_RIN1_N: C268.1 R18.2
C_CAM10_RIN1_P: C269.1 FL17.2 J11.1
C_CAM11_RIN2_N: C266.1 R7.2
C_CAM11_RIN2_P: C267.1 FL9.2 J8.1
C_CAM12_RIN3_N: C264.1 R1.2
C_CAM12_RIN3_P: C265.1 FL1.2 J5.1
CAM5_RIN0_N: C262.2 ; also on sheet 5
CAM5_RIN0_P: C260.2 ; also on sheet 5
CAM6_RIN1_N: C281.2 ; also on sheet 5
CAM6_RIN1_P: C274.2 ; also on sheet 5
CAM7_RIN2_N: C288.2 ; also on sheet 5
CAM7_RIN2_P: C285.2 ; also on sheet 5
CAM8_RIN3_N: C297.2 ; also on sheet 5
CAM8_RIN3_P: C292.2 ; also on sheet 5
CAM9_RIN0_N: C270.2 ; also on sheet 6
CAM9_RIN0_P: C271.2 ; also on sheet 6
CAM10_RIN1_N: C268.2 ; also on sheet 6
CAM10_RIN1_P: C269.2 ; also on sheet 6
CAM11_RIN2_N: C266.2 ; also on sheet 6
CAM11_RIN2_P: C267.2 ; also on sheet 6
CAM12_RIN3_N: C264.2 ; also on sheet 6
CAM12_RIN3_P: C265.2 ; also on sheet 6
V_CAM5: C60.1 C64.1 C232.1 FL35.1 R150.1 U18.4(OUT1) U18.5(OUT2) U18.6(OUT3) U18.7(OUT4) U18.8(OUT5)
V_CAM6: C76.1 C81.1 C250.1 FL43.1 R169.1 U23.4(OUT1) U23.5(OUT2) U23.6(OUT3) U23.7(OUT4) U23.8(OUT5)
V_CAM7: C107.1 C108.1 C314.1 FL47.1 R188.1 U26.4(OUT1) U26.5(OUT2) U26.6(OUT3) U26.7(OUT4) U26.8(OUT5)
V_CAM8: C116.1 C117.1 C340.1 FL51.1 R195.1 U27.4(OUT1) U27.5(OUT2) U27.6(OUT3) U27.7(OUT4) U27.8(OUT5)
V_CAM9: C57.1 C58.1 C224.1 FL34.1 R121.1 U16.4(OUT1) U16.5(OUT2) U16.6(OUT3) U16.7(OUT4) U16.8(OUT5)
V_CAM10: C38.1 C39.1 C211.1 FL23.1 R102.1 U12.4(OUT1) U12.5(OUT2) U12.6(OUT3) U12.7(OUT4) U12.8(OUT5)
V_CAM11: C18.1 C19.1 C168.1 FL15.1 R78.1 U7.4(OUT1) U7.5(OUT2) U7.6(OUT3) U7.7(OUT4) U7.8(OUT5)
V_CAM12: C9.1 C10.1 C137.1 FL7.1 R57.1 U3.4(OUT1) U3.5(OUT2) U3.6(OUT3) U3.7(OUT4) U3.8(OUT5)
N23304842: FL37.1 L14.2 R32.2
N23304854: C63.1 C65.1 FL35.2 L14.1 R32.1
N23304868: FL36.2 FL38.1
N23304877: FL36.1 FL37.2
N23306297: FL45.1 L15.2 R40.2
N23306309: C87.1 C92.1 FL43.2 L15.1 R40.1
N23306323: FL44.2 FL46.1
N23306330: FL44.1 FL45.2
N23308323: FL49.1 L16.2 R45.2
N23308335: C111.1 C112.1 FL47.2 L16.1 R45.1
N23308349: FL48.2 FL50.1
N23308356: FL48.1 FL49.2
N23309323: FL53.1 L17.2 R49.2
N23309335: C120.1 C121.1 FL51.2 L17.1 R49.1
N23309349: FL52.2 FL54.1
N23309356: FL52.1 FL53.2
N23319711: R131.1 R132.2 U18.14(EN/UVLO)
N23319731: R130.1 R131.2 U18.15(OVP)
N23319762: C233.1 U18.18(DVDT)
N23319779: R135.1 U18.17(ILIM)
N23319811: R141.1 U18.19(IMON)
N23319923: R150.2 U18.20(~{FLT})
N23320313: R163.1 R164.2 U23.14(EN/UVLO)
N23320339: R162.1 R163.2 U23.15(OVP)
N23320379: C253.1 U23.18(DVDT)
N23320395: R166.1 U23.17(ILIM)
N23320426: R168.1 U23.19(IMON)
N23320539: R169.2 U23.20(~{FLT})
N23320826: R182.1 R183.2 U26.14(EN/UVLO)
N23320852: R181.1 R182.2 U26.15(OVP)
N23320892: C312.1 U26.18(DVDT)
N23320908: R184.1 U26.17(ILIM)
N23320939: R187.1 U26.19(IMON)
N23321052: R188.2 U26.20(~{FLT})
N23321397: R190.1 R191.2 U27.14(EN/UVLO)
N23321423: R189.1 R190.2 U27.15(OVP)
N23321463: C339.1 U27.18(DVDT)
N23321479: R192.1 U27.17(ILIM)
N23321510: R194.1 U27.19(IMON)
N23321623: R195.2 U27.20(~{FLT})
N23545074: FL29.1 L12.2 R30.2
N23545086: C49.1 C50.1 FL34.2 L12.1 R30.1
N23545100: FL27.1 FL31.2
N23545106: FL29.2 FL31.1
N23545339: FL19.1 L9.2 R24.2
N23545354: C32.1 C33.1 FL23.2 L9.1 R24.1
N23545368: FL17.1 FL20.2
N23545374: FL19.2 FL20.1
N23545556: R138.2 R139.1 U16.14(EN/UVLO)
N23545576: R139.2 R140.1 U16.15(OVP)
N23545607: C231.1 U16.18(DVDT)
N23545624: R136.1 U16.17(ILIM)
N23545648: R128.1 U16.19(IMON)
N23545749: R121.2 U16.20(~{FLT})
N23545784: R113.2 R114.1 U12.14(EN/UVLO)
N23545810: R114.2 R115.1 U12.15(OVP)
N23545851: C210.1 U12.18(DVDT)
N23545860: R112.1 U12.17(ILIM)
N23545892: R106.1 U12.19(IMON)
N23546004: R102.2 U12.20(~{FLT})
N23546024: R91.2 R92.1 U7.14(EN/UVLO)
N23546050: R92.2 R93.1 U7.15(OVP)
N23546087: C164.1 U7.18(DVDT)
N23546094: R90.1 U7.17(ILIM)
N23546126: R81.1 U7.19(IMON)
N23546235: R78.2 U7.20(~{FLT})
N23546296: FL11.1 L5.2 R11.2
N23546308: C12.1 C13.1 FL15.2 L5.1 R11.1
N23546322: FL9.1 FL12.2
N23546328: FL11.2 FL12.1
N23546420: R67.2 R68.1 U3.14(EN/UVLO)
N23546459: R68.2 R69.1 U3.15(OVP)
N23546547: C136.1 U3.18(DVDT)
N23546577: R66.1 U3.17(ILIM)
N23546608: R61.1 U3.19(IMON)
N23546717: R57.2 U3.20(~{FLT})
N23546802: FL3.1 L2.2 R5.2
N23546814: C2.1 C3.1 FL7.2 L2.1 R5.1
N23546828: FL1.1 FL4.2
N23546834: FL3.2 FL4.1

Not connected (* = marked no-connect by the designer): U3 2(PGOOD); U7 2(PGOOD); U12 2(PGOOD); U16 2(PGOOD); U18 2(PGOOD); U23 2(PGOOD); U26 2(PGOOD); U27 2(PGOOD)

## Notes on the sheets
sheet 8
- FPD Link Camera  Inputs 5-8
- eFUSE
- Power Over Coax
- Camera Inputs to DS90UB9702
  (Deserializer U4)
- Silkscreen for J10:
  "CAMERA CONN 5"
- 100E
- Current limit
  set to 600 mA
- Power Over Coax
- Silkscreen for J11:
  "CAMERA CONN 6"
- 100E
- Current limit
  set to 600 mA
- Power Over Coax
- Silkscreen for J12:
  "CAMERA CONN 7"
- 100E
- Current limit
  set to 600 mA
- Power Over Coax
- Silkscreen for J13:
  "CAMERA CONN 8"
- Current limit
  set to 600 mA
- 100E
sheet 9
- FPD Link Camera  Inputs 9-12
- eFUSE
- Power Over Coax
- Camera Inputs to DS90UB9702
  (Deserializer U114)
- Silkscreen for J17:
  "CAMERA CONN 9"
- 100E
- Current limit
  set to 600 mA
- Power Over Coax
- Silkscreen for J18:
  "CAMERA CONN 10"
- 100E
- Current limit
  set to 600 mA
- Power Over Coax
- Silkscreen for J19:
  "CAMERA CONN 11"
- 100E
- Current limit
  set to 600 mA
- Power Over Coax
- Silkscreen for J20:
  "CAMERA CONN 12"
- 100E
- Current limit
  set to 600 mA
